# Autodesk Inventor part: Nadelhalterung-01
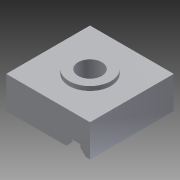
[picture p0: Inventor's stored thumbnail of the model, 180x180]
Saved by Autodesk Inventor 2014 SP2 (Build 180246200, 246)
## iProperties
Company: VDW-Nachwuchsstiftung
Created: 2014-04
Part Number: Nadelhalterung-01
Project: Verstellbarer Werkstückanschlag
Material: Aluminium 6061
Document SubType Name: Modeling
Designer: e_dammj
Density: 2.71 g/cm^3
Appearance: Aluminium - flach
Mass: 24.5784 g
Surface Area: 36.3222 cm^2
Volume: 9.06953 cm^3
Title: Nadelhalterung
Author: e_dammj
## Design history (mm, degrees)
derived "Nadelhalterung.ipt"
feature "Volumenkörper1::Nadelhalterung.ipt"
tag "Bezeichnung1"
node "Volumenkörper1"
other parameters: "d2" = 11.5, "d3" = 0, "d4" = 15, "d5" = 1.5, "d6" = 0, "d7" = 8.5, "d9" = 15, "d10" = 3.5, "d15" = 3, "d17" = 1, "d18" = 3, "d19" = 45 deg, "d21" = 0, "d23" = 0, "d24" = 11.599
